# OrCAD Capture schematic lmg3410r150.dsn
size D; title: LMG3410R150; rev: 1.0; note: *
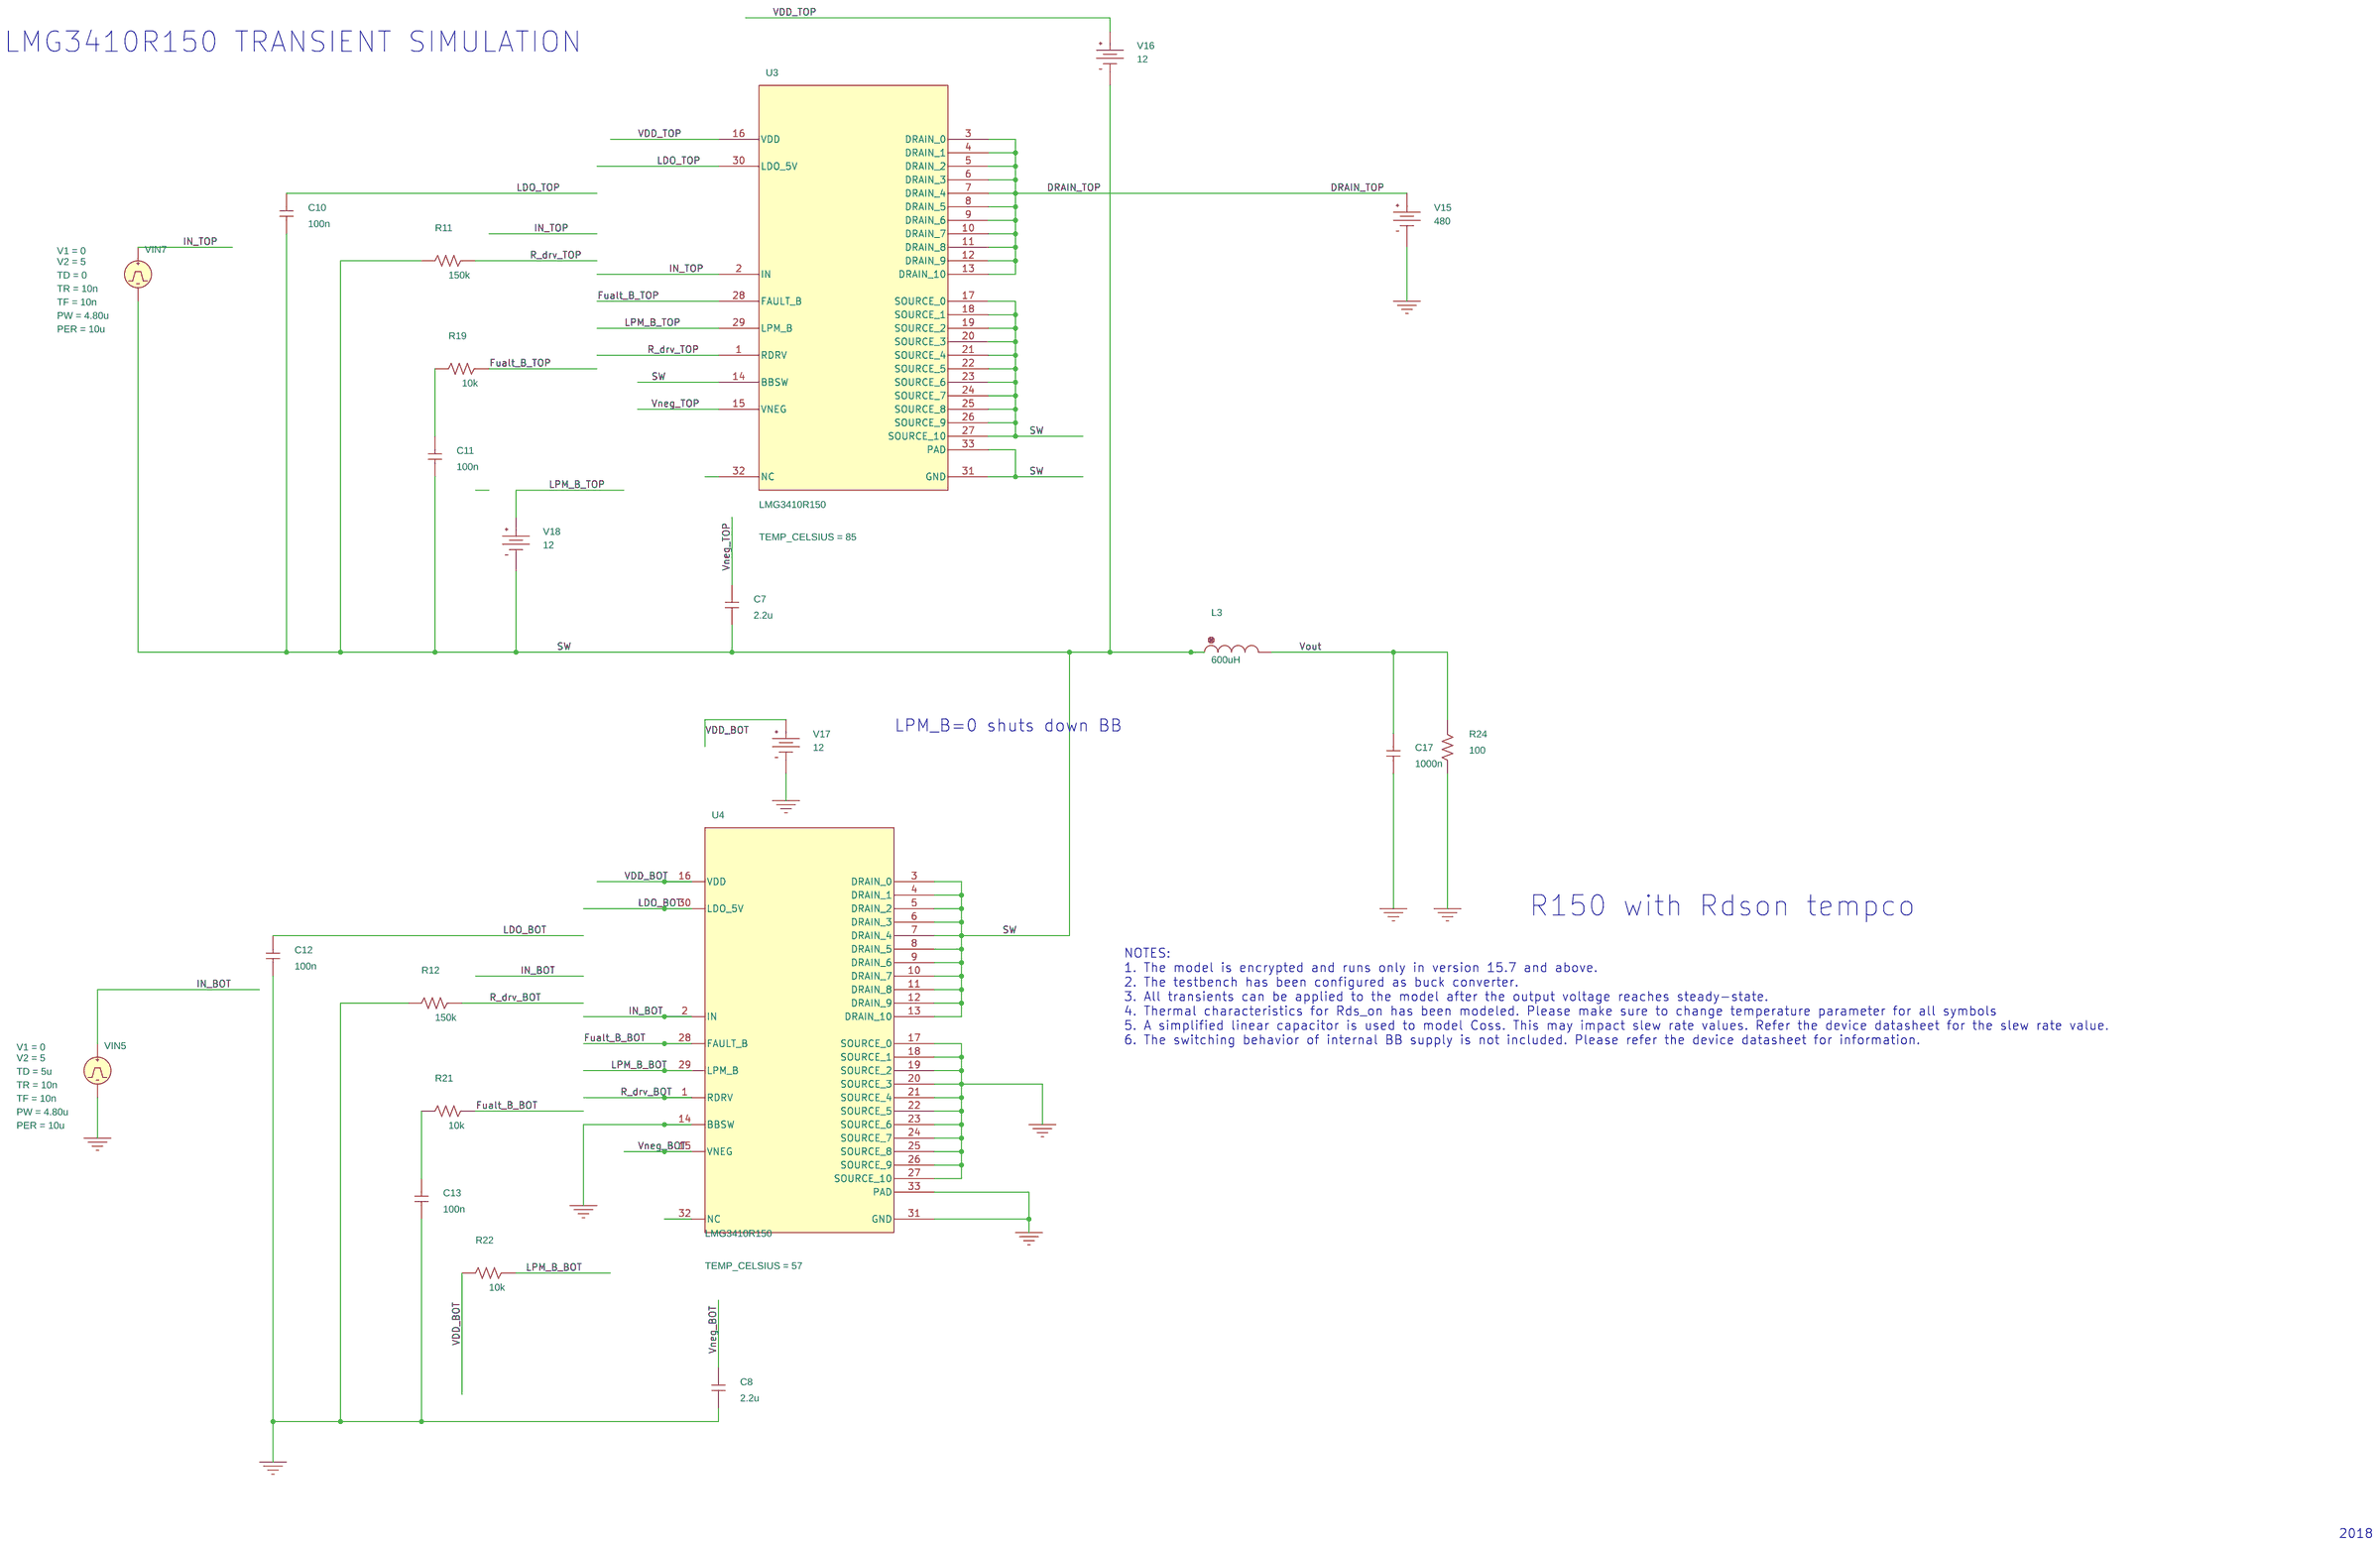
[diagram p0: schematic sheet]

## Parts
C7  2.2u  [RAD/CK05]
C8  2.2u  [RAD/CK05]
C10  100n  [RAD/CK05]
C11  100n  [RAD/CK05]
C12  100n  [RAD/CK05]
C13  100n  [RAD/CK05]
C17  1000n  [RAD/CK05]
L3  600uH  [DISC/.350x.175/LS.200x.100/.034]
R11  150k  [AX/RC05]
R12  150k  [AX/RC05]
R19  10k  [AX/RC05]
R21  10k  [AX/RC05]
R22  10k  [AX/RC05]
R24  100  [AX/RC05]
U3  LMG3410R150
U4  LMG3410R150
V15  VDC
V16  VDC
V17  VDC
V18  VDC
VIN5  VPULSE
VIN7  VPULSE

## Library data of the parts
C7 C8 C10-C13 C17 = C
L3 = L
R11 R12 R19 R21 R22 R24 = R
U3 = LMG3410R150_3: TEMP_CELSIUS: 85
U4 = LMG3410R150_3: TEMP_CELSIUS: 57
V15 = VDC: DC: 480
V16-V18 = VDC: DC: 12
VIN5 = VPULSE: PER: 10u; PW: 4.80u; TD: 5u; TF: 10n; TR: 10n; V1: 0; V2: 5
VIN7 = VPULSE: PER: 10u; PW: 4.80u; TD: 0; TF: 10n; TR: 10n; V1: 0; V2: 5

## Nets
VDD_BOT: R22.2 U4.16(VDD) V17.0(+)
VDD_TOP: U3.16(VDD) V16.0(+)
0: C8.1 C12.1 C13.1 C17.1 R12.2 R24.2 U4.14(BBSW) U4.17(SOURCE_0) U4.18(SOURCE_1) U4.19(SOURCE_2) U4.20(SOURCE_3) U4.21(SOURCE_4) U4.22(SOURCE_5) U4.23(SOURCE_6) U4.24(SOURCE_7) U4.25(SOURCE_8) U4.26(SOURCE_9) U4.27(SOURCE_10) U4.31(GND) U4.33(PAD) V15.1(-) V17.1(-) VIN5.2(-)
DRAIN_TOP: U3.3(DRAIN_0) U3.4(DRAIN_1) U3.5(DRAIN_2) U3.6(DRAIN_3) U3.7(DRAIN_4) U3.8(DRAIN_5) U3.9(DRAIN_6) U3.10(DRAIN_7) U3.11(DRAIN_8) U3.12(DRAIN_9) U3.13(DRAIN_10) V15.0(+)
Fualt_B_BOT: R21.1 U4.28(FAULT_B)
Fualt_B_TOP: R19.1 U3.28(FAULT_B)
IN_BOT: U4.2(IN) VIN5.1(+)
IN_TOP: U3.2(IN) VIN7.1(+)
LDO_BOT: C12.2 U4.30(LDO_5V)
LDO_TOP: C10.2 U3.30(LDO_5V)
LPM_B_BOT: R22.1 U4.29(LPM_B)
LPM_B_TOP: U3.29(LPM_B) V18.0(+)
R_drv_BOT: R12.1 U4.1(RDRV)
R_drv_TOP: R11.1 U3.1(RDRV)
SW: C7.1 C10.1 C11.1 L3.1 R11.2 U3.14(BBSW) U3.17(SOURCE_0) U3.18(SOURCE_1) U3.19(SOURCE_2) U3.20(SOURCE_3) U3.21(SOURCE_4) U3.22(SOURCE_5) U3.23(SOURCE_6) U3.24(SOURCE_7) U3.25(SOURCE_8) U3.26(SOURCE_9) U3.27(SOURCE_10) U3.31(GND) U3.33(PAD) U4.3(DRAIN_0) U4.4(DRAIN_1) U4.5(DRAIN_2) U4.6(DRAIN_3) U4.7(DRAIN_4) U4.8(DRAIN_5) U4.9(DRAIN_6) U4.10(DRAIN_7) U4.11(DRAIN_8) U4.12(DRAIN_9) U4.13(DRAIN_10) V16.1(-) V18.1(-) VIN7.2(-)
Vneg_BOT: C8.2 U4.15(VNEG)
Vneg_TOP: C7.2 U3.15(VNEG)
Vout: C17.2 L3.2 R24.1
N14584084: C13.2 R21.2
N14584296: C11.2 R19.2

Not connected (* = marked no-connect by the designer): U3 32(NC); U4 32(NC)

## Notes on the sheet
- LMG3410R150 TRANSIENT SIMULATION
- LPM_B=0 shuts down BB
- R150 with Rdson tempco
- NOTES:
  1. The model is encrypted and runs only in version 15.7 and above.
  2. The testbench has been configured as buck converter.
  3. All transients can be applied to the model after the output voltage reaches steady-state.
  4. Thermal characteristics for Rds_on has been modeled. Please make sure to change temperature parameter for all symbols
  5. A simplified linear capacitor is used to model Coss. This may impact slew rate values. Refer the device datasheet for the slew rate value.
  6. The switching behavior of internal BB supply is not included. Please refer the device datasheet for information.
- 2018
